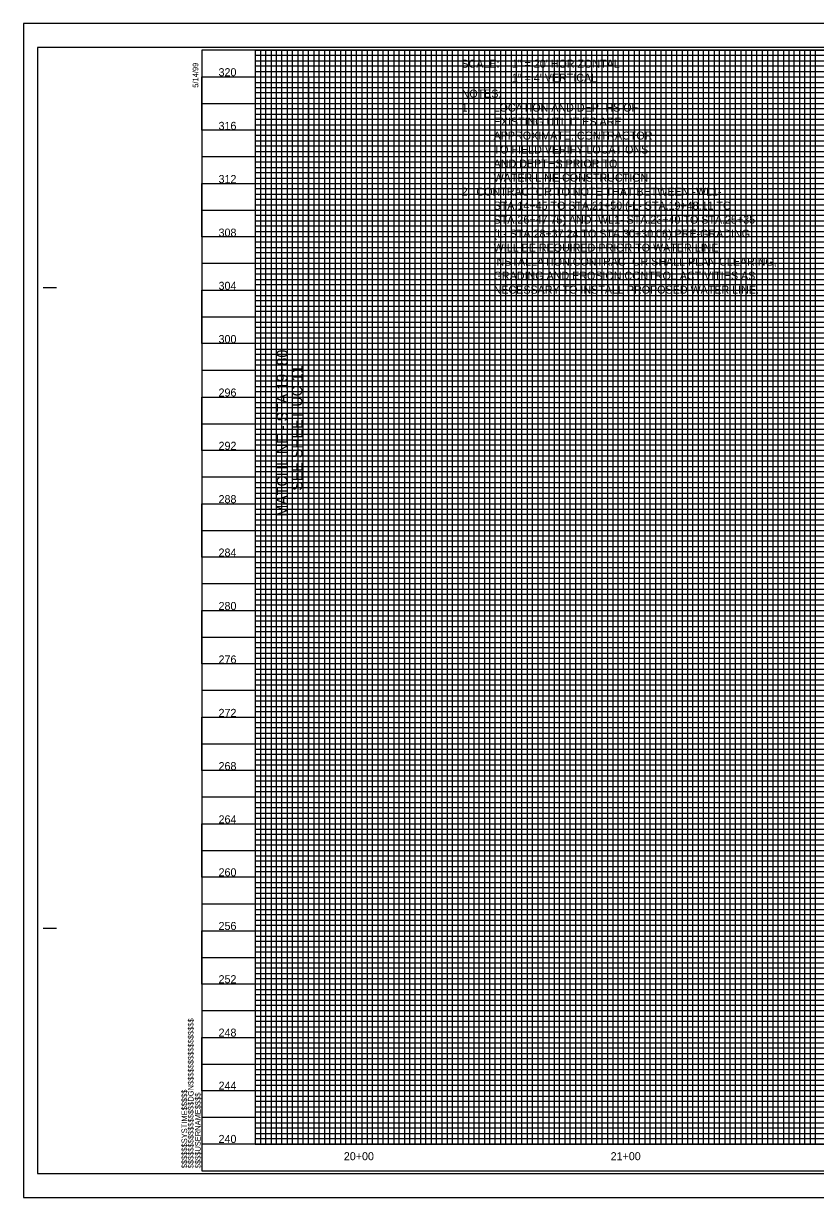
# Model space of a CAD drawing. Extents: x 1439200 to 3815465, y 598050 to 1224643.
# Drawn here: x 3814791.3 to 3815088.1, y 1224203.2 to 1224643.2 of the extents above; entities that cross this region are included whole.
import ezdxf

# ---------------------------------------------------------------- set-up
doc = ezdxf.new("R2010")
doc.units = 0
for name, color, linetype in [('COGO Default Spiral', 7, 'Continuous'), ('Exist Roads EOP', 7, 'Continuous'), ('General Text and Text Box and Leader Line', 7, 'Continuous'), ('Pattern 49', 7, 'Continuous'), ('Scratch_Level_1', 7, 'Continuous'), ('UC Full Profile Sheet 34 CELL', 7, 'Continuous'), ('Water Line Text and Text Box and Leader Line (St)', 7, 'Continuous'), ('Water Pump Station (St) CELL', 7, 'Continuous')]:
    doc.layers.add(name, color=color, linetype=linetype)

msp = doc.modelspace()

# ---------------------------------------------------------------- linework, layer by layer
at = {"layer": 'COGO Default Spiral'}
msp.add_line((3814898.11, 1224623.19), (3814898.11, 1224363.21), dxfattribs=at)
at = {"layer": 'Exist Roads EOP'}
for p, q in [((3814878.11, 1224633.21), (3815378.11, 1224633.21)), ((3815438.11, 1224561.21), (3814878.11, 1224561.21)), ((3814878.11, 1224561.21), (3814878.11, 1224559.21)), ((3814878.11, 1224559.21), (3815438.11, 1224559.21)), ((3815438.11, 1224551.21), (3814878.11, 1224551.21)), ((3814798.71, 1224544.21), (3814803.71, 1224544.21)), ((3814798.71, 1224304.21), (3814803.71, 1224304.21)), ((3815458.11, 1224223.21), (3814858.11, 1224223.21)), ((3814878.11, 1224223.21), (3815438.11, 1224223.21)), ((3814858.11, 1224213.21), (3814858.11, 1224213.21)), ((3814858.11, 1224213.21), (3814858.11, 1224213.21)), ((3814858.11, 1224213.21), (3814858.11, 1224213.21)), ((3814858.11, 1224213.21), (3814858.11, 1224213.21)), ((3814858.11, 1224213.21), (3814858.11, 1224213.21)), ((3814858.11, 1224213.21), (3814858.11, 1224213.21))]:
    msp.add_line(p, q, dxfattribs=at)
for points in [[(3815458.11, 1224633.21), (3814858.11, 1224633.21), (3814858.11, 1224213.21), (3815458.11, 1224213.21)], [(3814878.11, 1224633.21), (3814878.11, 1224223.21), (3815438.11, 1224223.21), (3815438.11, 1224578.19), (3815378.11, 1224578.19), (3815378.11, 1224633.21)]]:
    msp.add_lwpolyline(points, close=True, dxfattribs=at)
for points in [[(3814878.11, 1224633.21), (3814878.11, 1224223.21), (3814898.11, 1224223.21), (3814898.11, 1224633.21), (3814918.11, 1224633.21), (3814918.11, 1224223.21), (3814938.11, 1224223.21), (3814938.11, 1224633.21), (3814958.11, 1224633.21), (3814958.11, 1224223.21), (3814978.11, 1224223.21), (3814978.11, 1224633.21), (3814998.11, 1224633.21), (3814998.11, 1224223.21), (3815018.11, 1224223.21), (3815018.11, 1224633.21), (3815038.11, 1224633.21), (3815038.11, 1224223.21), (3815058.11, 1224223.21), (3815058.11, 1224633.21), (3815078.11, 1224633.21), (3815078.11, 1224223.21), (3815098.11, 1224223.21)], [(3814878.11, 1224633.21), (3814880.11, 1224633.21), (3814880.11, 1224223.21), (3814882.11, 1224223.21), (3814882.11, 1224633.21), (3814884.11, 1224633.21), (3814884.11, 1224223.21), (3814886.11, 1224223.21), (3814886.11, 1224633.21), (3814890.11, 1224633.21), (3814890.11, 1224223.21), (3814892.11, 1224223.21), (3814892.11, 1224633.21), (3814894.11, 1224633.21), (3814894.11, 1224223.21), (3814896.11, 1224223.21), (3814896.11, 1224633.21), (3814900.11, 1224633.21), (3814900.11, 1224223.21), (3814902.11, 1224223.21), (3814902.11, 1224633.21), (3814904.11, 1224633.21), (3814904.11, 1224223.21), (3814906.11, 1224223.21), (3814906.11, 1224633.21), (3814910.11, 1224633.21), (3814910.11, 1224223.21), (3814912.11, 1224223.21), (3814912.11, 1224633.21), (3814914.11, 1224633.21), (3814914.11, 1224223.21), (3814916.11, 1224223.21), (3814916.11, 1224633.21), (3814920.11, 1224633.21), (3814920.11, 1224223.21), (3814922.11, 1224223.21), (3814922.11, 1224633.21), (3814924.11, 1224633.21), (3814924.11, 1224223.21), (3814926.11, 1224223.21), (3814926.11, 1224633.21), (3814930.11, 1224633.21), (3814930.11, 1224223.21), (3814932.11, 1224223.21), (3814932.11, 1224633.21), (3814934.11, 1224633.21), (3814934.11, 1224223.21), (3814936.11, 1224223.21), (3814936.11, 1224633.21), (3814940.11, 1224633.21), (3814940.11, 1224223.21), (3814942.11, 1224223.21), (3814942.11, 1224633.21), (3814944.11, 1224633.21), (3814944.11, 1224223.21)], [(3815378.09, 1224631.21), (3814878.11, 1224631.21), (3814878.11, 1224629.21), (3815378.09, 1224629.21)], [(3814888.11, 1224223.21), (3814888.11, 1224633.21), (3814908.11, 1224633.21), (3814908.11, 1224223.21), (3814928.11, 1224223.21), (3814928.11, 1224633.21), (3814948.11, 1224633.21), (3814948.11, 1224223.21), (3814968.11, 1224223.21), (3814968.11, 1224633.21), (3814988.11, 1224633.21), (3814988.11, 1224223.21), (3815008.11, 1224223.21), (3815008.11, 1224633.21), (3815028.11, 1224633.21), (3815028.11, 1224223.21), (3815048.11, 1224223.21), (3815048.11, 1224633.21), (3815068.11, 1224633.21), (3815068.11, 1224223.21), (3815088.11, 1224223.21), (3815088.11, 1224633.21)], [(3814944.11, 1224223.21), (3814946.11, 1224223.21), (3814946.11, 1224633.21), (3814950.11, 1224633.21), (3814950.11, 1224223.21), (3814952.11, 1224223.21), (3814952.11, 1224633.21), (3814954.11, 1224633.21), (3814954.11, 1224223.21), (3814956.11, 1224223.21), (3814956.11, 1224633.21), (3814960.11, 1224633.21), (3814960.11, 1224223.21), (3814962.11, 1224223.21), (3814962.11, 1224633.21), (3814962.11, 1224633.21), (3814964.11, 1224633.21), (3814964.11, 1224223.21), (3814966.11, 1224223.21), (3814966.11, 1224633.21), (3814970.11, 1224633.21), (3814970.11, 1224223.21), (3814972.11, 1224223.21), (3814972.11, 1224633.21), (3814974.11, 1224633.21), (3814974.11, 1224223.21), (3814976.11, 1224223.21), (3814976.11, 1224633.21), (3814980.11, 1224633.21), (3814980.11, 1224223.21), (3814982.11, 1224223.21), (3814982.11, 1224633.21), (3814984.11, 1224633.21), (3814984.11, 1224223.21), (3814986.11, 1224223.21), (3814986.11, 1224633.21), (3814990.11, 1224633.21), (3814990.11, 1224223.21), (3814992.11, 1224223.21), (3814992.11, 1224633.21), (3814994.11, 1224633.21), (3814994.11, 1224223.21), (3814996.11, 1224223.21), (3814996.11, 1224633.21), (3815000.11, 1224633.21), (3815000.11, 1224223.21), (3815002.11, 1224223.21), (3815002.11, 1224633.21), (3815004.11, 1224633.21), (3815004.11, 1224223.21), (3815006.11, 1224223.21), (3815006.11, 1224633.21), (3815010.11, 1224633.21), (3815010.11, 1224223.21), (3815016.11, 1224223.21), (3815016.11, 1224633.21), (3815020.11, 1224633.21), (3815020.11, 1224223.21), (3815022.11, 1224223.21), (3815022.11, 1224633.21), (3815024.11, 1224633.21), (3815024.11, 1224223.21), (3815026.11, 1224223.21), (3815026.11, 1224633.21), (3815030.11, 1224633.21), (3815030.11, 1224223.21), (3815032.11, 1224223.21), (3815032.11, 1224633.21), (3815034.11, 1224633.21), (3815034.11, 1224223.21), (3815036.11, 1224223.21), (3815036.11, 1224633.21), (3815040.11, 1224633.21), (3815040.11, 1224223.21), (3815042.11, 1224223.21), (3815042.11, 1224633.21), (3815044.11, 1224633.21), (3815044.11, 1224223.21), (3815046.11, 1224223.21), (3815046.11, 1224633.21), (3815050.11, 1224633.21), (3815050.11, 1224223.21), (3815052.11, 1224223.21), (3815052.11, 1224633.21), (3815054.11, 1224633.21), (3815054.11, 1224223.21), (3815056.11, 1224223.21), (3815056.11, 1224633.21), (3815060.11, 1224633.21), (3815060.11, 1224223.21), (3815062.11, 1224223.21), (3815062.11, 1224633.21), (3815064.11, 1224633.21), (3815064.11, 1224223.21), (3815066.11, 1224223.21), (3815066.11, 1224633.21), (3815070.11, 1224633.21), (3815070.11, 1224223.21)], [(3815012.11, 1224633.21), (3815012.11, 1224223.21), (3815014.11, 1224223.21), (3815014.11, 1224633.21)], [(3815012.11, 1224632.97), (3815012.11, 1224223.21), (3815014.11, 1224223.21), (3815014.11, 1224632.97)], [(3815072.11, 1224633.21), (3815072.11, 1224223.21), (3815074.11, 1224223.21), (3815074.11, 1224633.21), (3815076.11, 1224633.21), (3815076.11, 1224223.21), (3815080.11, 1224223.21), (3815080.11, 1224633.21), (3815082.11, 1224633.21), (3815082.11, 1224223.21), (3815084.11, 1224223.21), (3815084.11, 1224633.21), (3815086.11, 1224633.21), (3815086.11, 1224223.21)], [(3815378.09, 1224627.21), (3814878.11, 1224627.21), (3814878.11, 1224625.21), (3815378.09, 1224625.21)], [(3815378.09, 1224603.21), (3814858.15, 1224603.21), (3814858.15, 1224623.19), (3815378.09, 1224623.19)], [(3815378.09, 1224620.91), (3814878.11, 1224620.91), (3814878.11, 1224619.21), (3815378.09, 1224619.21)], [(3815378.09, 1224617.21), (3814878.11, 1224617.21), (3814878.11, 1224615.21), (3815378.09, 1224615.21)], [(3814858.11, 1224613.21), (3815378.09, 1224613.21)], [(3815378.09, 1224611.21), (3814878.11, 1224611.21), (3814878.11, 1224609.21), (3815378.09, 1224609.21)], [(3815378.11, 1224607.21), (3814878.11, 1224607.21), (3814878.11, 1224605.21), (3815378.09, 1224605.21)], [(3815378.09, 1224601.21), (3814878.11, 1224601.21), (3814878.11, 1224599.21), (3815378.09, 1224599.21)], [(3815378.09, 1224597.21), (3814878.11, 1224597.21), (3814878.11, 1224595.21), (3815378.09, 1224595.21)], [(3815378.09, 1224593.21), (3814858.11, 1224593.21), (3814858.11, 1224573.19), (3815458.11, 1224573.19)], [(3815378.09, 1224591.21), (3814878.11, 1224591.21), (3814878.11, 1224589.21), (3815378.09, 1224589.21)], [(3815378.09, 1224587.21), (3814878.11, 1224587.21), (3814878.11, 1224585.21), (3815378.09, 1224585.21)], [(3815458.11, 1224563.21), (3814858.11, 1224563.21), (3814858.11, 1224583.21), (3815378.09, 1224583.21)], [(3815378.09, 1224581.21), (3814878.11, 1224581.21), (3814878.11, 1224579.21), (3815378.09, 1224579.21)], [(3815438.11, 1224577.21), (3814878.11, 1224577.21), (3814878.11, 1224577.21), (3814878.11, 1224569.21), (3815438.11, 1224569.21)], [(3815438.11, 1224577.21), (3814878.11, 1224577.21), (3814878.11, 1224577.21), (3814878.11, 1224569.21), (3815458.11, 1224569.21)], [(3814878.11, 1224575.21), (3815438.11, 1224575.21)], [(3815438.11, 1224571.21), (3814878.11, 1224571.21)], [(3815438.11, 1224567.21), (3814878.11, 1224567.21), (3814878.11, 1224565.21), (3815438.11, 1224565.21)], [(3815438.11, 1224557.21), (3814878.11, 1224557.21), (3814878.11, 1224555.21), (3815438.11, 1224555.21)], [(3815458.11, 1224553.21), (3814858.11, 1224553.21), (3814858.11, 1224533.21), (3815458.11, 1224533.21)], [(3815438.11, 1224549.21), (3814878.11, 1224549.21), (3814878.11, 1224547.21), (3815438.11, 1224547.21)], [(3815458.11, 1224523.21), (3814858.11, 1224523.21), (3814858.11, 1224543.21), (3815458.11, 1224543.21)], [(3815438.11, 1224545.21), (3814878.11, 1224545.21)], [(3814878.11, 1224541.21), (3815438.11, 1224541.21)], [(3815438.11, 1224539.21), (3814878.11, 1224539.21), (3814878.11, 1224537.21), (3815438.11, 1224537.21)], [(3815438.11, 1224535.21), (3814878.11, 1224535.21), (3814878.11, 1224531.21), (3815438.11, 1224531.21)], [(3815438.11, 1224529.21), (3814878.11, 1224529.21), (3814878.11, 1224527.21), (3815438.11, 1224527.21)], [(3815438.11, 1224525.21), (3814878.11, 1224525.21), (3814878.11, 1224521.21), (3815438.11, 1224521.21)], [(3815438.11, 1224519.21), (3814878.11, 1224519.21), (3814878.11, 1224517.21), (3815438.11, 1224517.21)], [(3815458.11, 1224513.21), (3814858.11, 1224513.21), (3814858.11, 1224493.21), (3815458.11, 1224493.21)], [(3815438.11, 1224515.21), (3814878.11, 1224515.21), (3814878.11, 1224511.21), (3815438.11, 1224511.21)], [(3815438.11, 1224509.21), (3814878.11, 1224509.21), (3814878.11, 1224507.21), (3815438.11, 1224507.21)], [(3815458.11, 1224483.21), (3814858.11, 1224483.21), (3814858.11, 1224503.21), (3815458.11, 1224503.21)], [(3815438.11, 1224505.21), (3814878.11, 1224505.21), (3814878.11, 1224501.21), (3815438.11, 1224501.21)], [(3815438.11, 1224499.21), (3814878.11, 1224499.21), (3814878.11, 1224497.21), (3815438.11, 1224497.21)], [(3815438.11, 1224495.21), (3814878.11, 1224495.21), (3814878.11, 1224491.21), (3815438.11, 1224491.21)], [(3815438.11, 1224489.21), (3814878.11, 1224489.21), (3814878.11, 1224487.21), (3815438.11, 1224487.21)], [(3815438.11, 1224485.21), (3814878.11, 1224485.21), (3814878.11, 1224481.21), (3815438.11, 1224481.21)], [(3815438.11, 1224479.21), (3814878.11, 1224479.21), (3814878.11, 1224477.21), (3815438.11, 1224477.21)], [(3815458.11, 1224473.21), (3814858.11, 1224473.21), (3814858.11, 1224453.21), (3815458.11, 1224453.21)], [(3815438.11, 1224475.21), (3814878.11, 1224475.21), (3814878.11, 1224471.21), (3815438.11, 1224471.21)], [(3815438.11, 1224469.21), (3814878.11, 1224469.21), (3814878.11, 1224467.21), (3815438.11, 1224467.21)], [(3815458.11, 1224443.21), (3814858.11, 1224443.21), (3814858.11, 1224463.21), (3815458.11, 1224463.21)], [(3815438.11, 1224465.21), (3814878.11, 1224465.21), (3814878.11, 1224461.21), (3815438.11, 1224461.21)], [(3815438.11, 1224459.21), (3814878.11, 1224459.21), (3814878.11, 1224457.21), (3815438.11, 1224457.21)], [(3815438.11, 1224455.21), (3814878.11, 1224455.21), (3814878.11, 1224451.21), (3815438.11, 1224451.21)], [(3815438.11, 1224449.21), (3814878.11, 1224449.21), (3814878.11, 1224447.21), (3815438.11, 1224447.21)], [(3815438.11, 1224445.21), (3814878.11, 1224445.21), (3814878.11, 1224441.21), (3815438.11, 1224441.21)], [(3815438.11, 1224439.21), (3814878.11, 1224439.21), (3814878.11, 1224437.21), (3815438.11, 1224437.21)], [(3815458.11, 1224433.21), (3814858.11, 1224433.21), (3814858.11, 1224413.21), (3815458.11, 1224413.21)], [(3815438.11, 1224435.21), (3814878.11, 1224435.21), (3814878.11, 1224431.21), (3815438.11, 1224431.21)], [(3815438.11, 1224429.21), (3814878.11, 1224429.21), (3814878.11, 1224427.21), (3815438.11, 1224427.21)], [(3815458.11, 1224403.21), (3814858.11, 1224403.21), (3814858.11, 1224423.21), (3815458.11, 1224423.21)], [(3815438.11, 1224425.21), (3814878.11, 1224425.21)], [(3814878.11, 1224421.21), (3815438.11, 1224421.21)], [(3815438.11, 1224419.21), (3814878.11, 1224419.21), (3814878.11, 1224417.21), (3815438.11, 1224417.21)], [(3815438.11, 1224415.21), (3814878.11, 1224415.21), (3814878.11, 1224411.21), (3815438.11, 1224411.21)], [(3815438.11, 1224409.21), (3814878.11, 1224409.21), (3814878.11, 1224407.21), (3815438.11, 1224407.21)], [(3815438.11, 1224405.21), (3814878.11, 1224405.21), (3814878.11, 1224401.21), (3815438.11, 1224401.21)], [(3815438.11, 1224399.21), (3814878.11, 1224399.21), (3814878.11, 1224397.21), (3815438.11, 1224397.21)], [(3815458.11, 1224393.21), (3814858.11, 1224393.21), (3814858.11, 1224373.21), (3815458.11, 1224373.21)], [(3815438.11, 1224395.21), (3814878.11, 1224395.21), (3814878.11, 1224391.21), (3815438.11, 1224391.21)], [(3815438.11, 1224389.21), (3814878.11, 1224389.21), (3814878.11, 1224387.21), (3815438.11, 1224387.21)], [(3815438.11, 1224385.21), (3814878.11, 1224385.21), (3814878.11, 1224381.21), (3815438.11, 1224381.21)], [(3815458.11, 1224363.21), (3814858.11, 1224363.21), (3814858.11, 1224383.21), (3815458.11, 1224383.21)], [(3815438.11, 1224379.21), (3814878.11, 1224379.21), (3814878.11, 1224377.21), (3815438.11, 1224377.21)], [(3815438.11, 1224375.21), (3814878.11, 1224375.21), (3814878.11, 1224371.21), (3815438.11, 1224371.21)], [(3815438.11, 1224369.21), (3814878.11, 1224369.21), (3814878.11, 1224367.21), (3815438.11, 1224367.21)], [(3815438.11, 1224365.21), (3814878.11, 1224365.21), (3814878.11, 1224361.21), (3815438.11, 1224361.21)], [(3815438.11, 1224359.21), (3814878.11, 1224359.21), (3814878.11, 1224357.21), (3815438.11, 1224357.21)], [(3815458.11, 1224353.21), (3814858.11, 1224353.21), (3814858.11, 1224333.21), (3815458.11, 1224333.21)], [(3815438.11, 1224355.21), (3814878.11, 1224355.21), (3814878.11, 1224351.21), (3815438.11, 1224351.21)], [(3815438.11, 1224349.21), (3814878.11, 1224349.21), (3814878.11, 1224347.21), (3815438.11, 1224347.21)], [(3815438.11, 1224345.21), (3814878.11, 1224345.21), (3814878.11, 1224341.21), (3815438.11, 1224341.21)], [(3815458.11, 1224323.21), (3814858.11, 1224323.21), (3814858.11, 1224343.21), (3815458.11, 1224343.21)], [(3815438.11, 1224339.21), (3814878.11, 1224339.21), (3814878.11, 1224337.21), (3815438.11, 1224337.21)], [(3815438.11, 1224335.21), (3814878.11, 1224335.21), (3814878.11, 1224331.21), (3815438.11, 1224331.21)], [(3815438.11, 1224329.21), (3814878.11, 1224329.21), (3814878.11, 1224327.21), (3815438.11, 1224327.21)], [(3815438.11, 1224325.21), (3814878.11, 1224325.21), (3814878.11, 1224321.21), (3815438.11, 1224321.21)], [(3815438.11, 1224319.21), (3814878.11, 1224319.21), (3814878.11, 1224317.21), (3815438.11, 1224317.21)], [(3815458.11, 1224313.21), (3814858.11, 1224313.21), (3814858.11, 1224293.21), (3815458.11, 1224293.21)], [(3815438.11, 1224315.21), (3814878.11, 1224315.21), (3814878.11, 1224311.21), (3815438.11, 1224311.21)], [(3815438.11, 1224309.21), (3814878.11, 1224309.21), (3814878.11, 1224307.21), (3815438.11, 1224307.21)], [(3815438.11, 1224305.21), (3814878.11, 1224305.21)], [(3815458.11, 1224283.21), (3814858.11, 1224283.21), (3814858.11, 1224303.21), (3815458.11, 1224303.21)], [(3814878.11, 1224301.21), (3815438.11, 1224301.21)], [(3815438.11, 1224299.21), (3814878.11, 1224299.21), (3814878.11, 1224297.21), (3815438.11, 1224297.21)], [(3815438.11, 1224295.21), (3814878.11, 1224295.21)], [(3814878.11, 1224291.21), (3815438.11, 1224291.21)], [(3815438.11, 1224289.21), (3814878.11, 1224289.21), (3814878.11, 1224287.21), (3815438.11, 1224287.21)], [(3815438.11, 1224285.21), (3814878.11, 1224285.21), (3814878.11, 1224281.21), (3815438.11, 1224281.21)], [(3815438.11, 1224279.21), (3814878.11, 1224279.21), (3814878.11, 1224277.21), (3815438.11, 1224277.21)], [(3815438.11, 1224275.21), (3814878.11, 1224275.21), (3814878.11, 1224271.21), (3815438.11, 1224271.21)], [(3815458.11, 1224273.21), (3814858.11, 1224273.21), (3814858.11, 1224253.21), (3815458.11, 1224253.21)], [(3815438.11, 1224269.21), (3814878.11, 1224269.21), (3814878.11, 1224267.21), (3815438.11, 1224267.21)], [(3815438.11, 1224265.21), (3814878.11, 1224265.21), (3814878.11, 1224261.21), (3815438.11, 1224261.21)], [(3815458.11, 1224243.21), (3814858.11, 1224243.21), (3814858.11, 1224263.21), (3815458.11, 1224263.21)], [(3815438.11, 1224259.21), (3814878.11, 1224259.21), (3814878.11, 1224257.21), (3815438.11, 1224257.21)], [(3815438.11, 1224255.21), (3814878.11, 1224255.21), (3814878.11, 1224251.21), (3815438.11, 1224251.21)], [(3815438.11, 1224249.21), (3814878.11, 1224249.21), (3814878.11, 1224247.21), (3815438.11, 1224247.21)], [(3815438.11, 1224245.21), (3814878.11, 1224245.21), (3814878.11, 1224241.21), (3815438.11, 1224241.21)], [(3815438.11, 1224239.21), (3814878.11, 1224239.21), (3814878.11, 1224237.21), (3815438.11, 1224237.21)], [(3815438.11, 1224235.21), (3814878.11, 1224235.21), (3814878.11, 1224231.21), (3815438.11, 1224231.21)], [(3815458.11, 1224233.21), (3814858.11, 1224233.21)], [(3815438.11, 1224229.21), (3814878.11, 1224229.21), (3814878.11, 1224227.21), (3815438.11, 1224227.21)], [(3815438.11, 1224225.21), (3814878.11, 1224225.21)], [(3814873.11, 1224213.21), (3814873.11, 1224213.21)]]:
    msp.add_lwpolyline(points, dxfattribs=at)
at = {"layer": 'Pattern 49'}
msp.add_lwpolyline([(3815463.11, 1224634.23), (3814796.51, 1224634.23), (3814796.51, 1224212.19), (3815463.11, 1224212.19)], close=True, dxfattribs=at)
at = {"layer": 'Scratch_Level_1'}
msp.add_lwpolyline([(3815464.91, 1224643.21), (3814791.31, 1224643.21), (3814791.31, 1224203.21), (3815464.91, 1224203.21)], close=True, dxfattribs=at)

# ---------------------------------------------------------------- texts
at = {"layer": 'Exist Roads EOP'}
for s, p in [('5/14/99', (3814856.81, 1224619.13)), ('$$$$$$$$$$$$$$$$DGN$$$$$$$$$$$$$$$$', (3814855.05, 1224214.15)), ('$$$$$$SYSTIME$$$$$', (3814852.63, 1224214.15)), ('$$$$USERNAME$$$$', (3814857.68, 1224214.16))]:
    msp.add_text(s, height=2.1, rotation=90, dxfattribs=at).set_placement(p)
at = {"layer": 'General Text and Text Box and Leader Line'}
for s, p in [('320', (3814864.41, 1224623.44)), ('316', (3814864.41, 1224603.34)), ('312', (3814864.41, 1224583.4)), ('308', (3814864.41, 1224563.33)), ('304', (3814864.41, 1224543.4)), ('300', (3814864.41, 1224523.43)), ('296', (3814864.41, 1224503.4)), ('292', (3814864.41, 1224483.44)), ('288', (3814864.41, 1224463.44)), ('284', (3814864.41, 1224443.43)), ('280', (3814864.41, 1224423.4)), ('276', (3814864.41, 1224403.36)), ('272', (3814864.41, 1224383.34)), ('268', (3814864.41, 1224363.39)), ('264', (3814864.41, 1224343.43)), ('260', (3814864.41, 1224323.59)), ('256', (3814864.41, 1224303.48)), ('252', (3814864.41, 1224283.52)), ('248', (3814864.41, 1224263.52)), ('244', (3814864.41, 1224243.62)), ('240', (3814864.41, 1224223.66))]:
    msp.add_text(s, height=3, dxfattribs=at).set_placement(p)
at = {"layer": 'UC Full Profile Sheet 34 CELL'}
for s, p in [('SCALE: ', (3814955.41, 1224626.62)), ('1" = 20\' HORIZONTAL', (3814974.31, 1224626.62)), ('1" = 4\' VERTICAL', (3814974.31, 1224621.37)), ('NOTES:', (3814955.48, 1224615.43)), ('1.', (3814955.48, 1224610.18)), ('LOCATION AND DEPTHS OF', (3814967.48, 1224610.18)), ('EXISTING UTILITIES ARE', (3814967.48, 1224604.94)), ('APPROXIMATE. CONTRACTOR', (3814967.48, 1224599.69)), ('TO FIELD VERIFY LOCATIONS', (3814967.48, 1224594.44)), ('AND DEPTHS PRIOR TO', (3814967.48, 1224589.19)), ('WATER LINE CONSTRUCTION.', (3814967.48, 1224583.94)), ('2.  CONTRACTOR TO NOTE THAT BETWEEN -WL1-', (3814955.48, 1224578.69)), ('STA.14+45 TO STA.21+50 (-L- STA.19+48.11 TO', (3814967.48, 1224573.44)), ('STA.26+47.75) AND -WL1- STA.23+40 TO STA.25+35', (3814967.48, 1224568.2)), ('(L- STA.28+37.24 TO STA.30+30.06) PRE-GRADING', (3814967.48, 1224562.95)), ('WILL BE REQUIRED PRIOR TO WATER LINE', (3814967.48, 1224557.7)), ('INSTALLATION.CONTRACTOR SHALL PLAN CLEARING,', (3814967.48, 1224552.45)), ('GRADING AND EROSION CONTROL ACTIVITIES AS', (3814967.48, 1224547.2)), ('NECESSARY TO INSTALL PROPOSED WATER LINE.', (3814967.48, 1224541.95))]:
    msp.add_text(s, height=3, dxfattribs=at).set_placement(p)
at = {"layer": 'Water Line Text and Text Box and Leader Line (St)'}
for s, p in [('MATCHLINE - STA.19+80', (3814890.21, 1224458.38)), ('SEE SHEET UC-11', (3814895.81, 1224468.1))]:
    msp.add_text(s, height=4, rotation=90, dxfattribs=at).set_placement(p)
at = {"layer": 'Water Pump Station (St) CELL'}
for s, p in [('20+00', (3814911.36, 1224217.19)), ('21+00', (3815011.34, 1224217.19))]:
    msp.add_text(s, height=3, dxfattribs=at).set_placement(p)

doc.saveas('drawing.dxf')
